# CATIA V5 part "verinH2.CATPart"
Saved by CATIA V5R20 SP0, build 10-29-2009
Part number: verinH2
Bounding box of the stored display mesh (mm): x -15 to 15, y -39.374 to 70, z 578.303 to 1189.977
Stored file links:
  D:\Dropbox\Pack 1 sylvain\mmoreau\mmoreau\mmoreau\fin\verinH2.CATPart
  U:\think motion\fin\think motion2.CATProduct
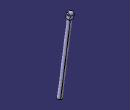
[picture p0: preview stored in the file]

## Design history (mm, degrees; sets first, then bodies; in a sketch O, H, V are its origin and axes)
Set1
  Line1: linked copy from another document
  Point1: linked copy from another document
Body1 (main body)
  Sketch1 on yz-plane, origin (0, 0, 0), H (0, 1, 0), V (0, 0, 1)
    line L1 (40.1323, 1176.9877) -> (-39.3743, 582.2787)
    reference projected line E1 (55, 1175) -> (-24.5065, 580.2911) from Line1
    reference projected line E2 (55, 1175) -> (-24.5065, 580.2911) from Line1
    arc A1 centre (55, 1175) radius 15 from (56.9877, 1189.8677) to (40.1323, 1176.9877) ccw
    point P2 (55, 1175)
    reference projected point E3 (55, 1175) from Point1
    axis line L2 (63.4071, 1237.8853) -> (53.0188, 1160.1806)
    reference projected line E4 (55, 1175) -> (-24.5065, 580.2911) from Line1
    point P6 (56.9877, 1189.8677)
    line L3 (-24.5065, 580.2911) -> (-39.3743, 582.2787)
    point P7 (-24.5065, 580.2911)
    reference projected line E5 (55, 1175) -> (-24.5065, 580.2911) from Line1
    reference projected point E6 (55, 1175) from Point1
    distance E2 L1 = 15
    distance L3 E6 = 600
    parallelism: E1 L1, L2 L1
    coincidence: P2 E3, L2 E4, L2 P6, P7 E5
    tangency: L1 A1
    perpendicularity: L3 L1
  Shaft1: profile Sketch1, axis Sketch1.L2, angle 360
  Sketch2 on yz-plane, origin (0, 0, 0), H (0, 1, 0), V (0, 0, 1)
    circle A1 centre (55, 1175) radius 5
    point P1 (55, 1175)
    reference projected point E1 (55, 1175) from Point1
    radius A1 = 5
    coincidence: P1 E1
  Pocket1: profile Sketch2, direction (-1, 0, 0), length 20, mirrored extent
  Sketch3 on yz-plane, origin (0, 0, 0), H (0, 1, 0), V (0, 0, 1)
    line L1 (40.1323, 1176.9877) -> (36.1569, 1147.2522)
    line L2 (36.1569, 1147.2522) -> (65.8924, 1143.2769)
    line L3 (65.8924, 1143.2769) -> (69.8677, 1173.0123)
    reference projected line E1 (55, 1175) -> (-24.5065, 580.2911) from Line1
    arc A1 centre (55, 1175) radius 15 from (69.8677, 1173.0123) to (40.1323, 1176.9877) ccw
    point P3 (55, 1175)
    reference projected point E2 (55, 1175) from Point1
    reference projected point E3 (55, 1175) from Point1
    circle A2 centre (55, 1175) radius 5
    point P6 (55, 1175)
    reference projected point E4 (55, 1175) from Point1
    reference projected arc E5 centre (55, 1175) radius 5 from (59.9559, 1174.3374) to (50.0441, 1175.6626) ccw from edge [face of Pocket1 from Sketch2.A1 | face of Shaft1 from Sketch1.A1]
    distance L1 L3 = 30
    radius A1 = 15
    distance L2 E3 = 30
    perpendicularity: L1 L2
    symmetry: L1 L3 E1
    coincidence: P3 E2, P6 E4, A2 E5
  Pad1: profile Sketch3, direction (-1, 0, 0), length 15, mirrored extent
